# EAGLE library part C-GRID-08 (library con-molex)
CONNECTOR wire to board 2.54 mm (0.100") pitch header
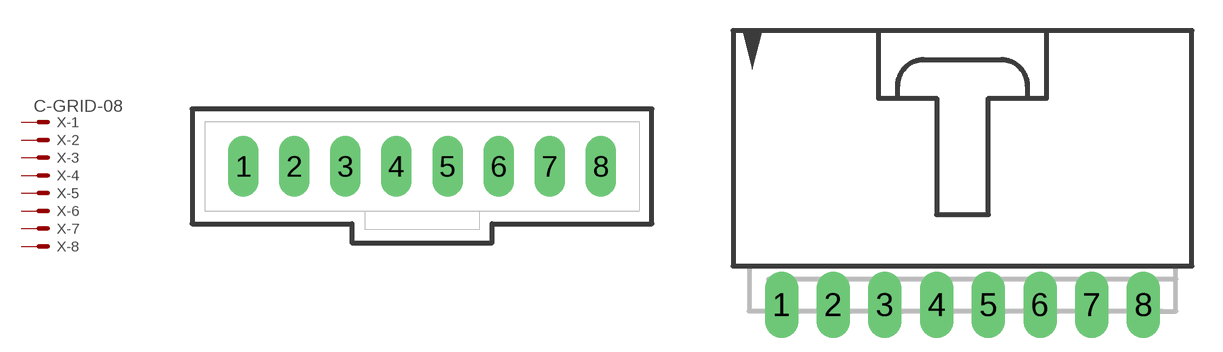
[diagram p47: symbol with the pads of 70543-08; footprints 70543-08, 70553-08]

Designator prefix X; gates -1=MV -2=M -3=M -4=M -5=M -6=M -7=M -8=M

## C-GRID-08-70543 (OC_FARNELL: unknown; OC_NEWARK: unknown)  [70543-08]
1  -1:S  pas
2  -2:S  pas
3  -3:S  pas
4  -4:S  pas
5  -5:S  pas
6  -6:S  pas
7  -7:S  pas
8  -8:S  pas

## C-GRID-08-70553 (OC_FARNELL: unknown; OC_NEWARK: unknown)  [70553-08]
Pads as for 70543-08

## C-GRID-08-74099 (OC_FARNELL: unknown; OC_NEWARK: unknown)  [74099-08]
Pads as for 70543-08

## C-GRID-08-15-91 (OC_FARNELL: unknown; OC_NEWARK: unknown)  [15-91-08]
Pads as for 70543-08

## Footprint 70543-08 (pad centres in mm)
C-Grid SL Connector vertical, 8 pin
drill 1.016 long: 1 -8.89,0; 2 -6.35,0; 3 -3.81,0; 4 -1.27,0; 5 1.27,0; 6 3.81,0; 7 6.35,0; 8 8.89,0

## Footprint 70553-08 (pad centres in mm)
C-Grid SL Connector right angle, 8 pin
drill 1.092 long: 1 -8.89,-7.62; 2 -6.35,-7.62; 3 -3.81,-7.62; 4 -1.27,-7.62; 5 1.27,-7.62; 6 3.81,-7.62; 7 6.35,-7.62; 8 8.89,-7.62

## Footprint 74099-08 (pad centres in mm)
C-Grid SL Connector vertical SMD, 8 pin
smd 1.27 x 3.175: 1 -8.89,-2.223; 2 -6.35,2.223; 3 -3.81,-2.223; 4 -1.27,2.223; 5 1.27,-2.223; 6 3.81,2.223; 7 6.35,-2.223; 8 8.89,2.223

## Footprint 15-91-08 (pad centres in mm)
C-Grid SL Connector right angle SMD, 8 pin
smd 1.651 x 5.334: 1 -8.89,-10.795; 2 -6.35,-10.795; 3 -3.81,-10.795; 4 -1.27,-10.795; 5 1.27,-10.795; 6 3.81,-10.795; 7 6.35,-10.795; 8 8.89,-10.795
hole 3.404 at -10.287,0.838
hole 3.404 at 10.287,0.838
